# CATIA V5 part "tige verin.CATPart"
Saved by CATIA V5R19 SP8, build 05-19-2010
Part number: tige verin
Bounding box of the stored display mesh (mm): x -10 to -2, y -3 to 13.607, z -16.853 to 8.502
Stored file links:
  C:\Users\rcousturie\Desktop\EU_thinkMotion\iao\IAO_MMS_Groupe1\glenerrant\glenerrant\Nouveau dossier\tige verin.CATPart
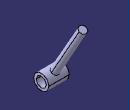
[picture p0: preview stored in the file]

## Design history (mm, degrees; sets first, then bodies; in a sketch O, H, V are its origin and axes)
Set1
  Point1: (0, 0, -14)
  Point2: (0, 13, 9)
  Plane1: type Offset, RefPlane yz-plane, Offset -2
  Plane2: type Normal, Curve Line1, RefPoint Point1
  Line1: stored without definition
Body1 (main body)
  Sketch1 on Plane1, origin (-2, 0, 0), H (0, 1, 0), V (0, 0, 1)
    circle A1 centre (0, -14) radius 3
    point P1 (0, -14)
    circle A2 centre (0, -14) radius 2
    point P2 (0, -14)
    reference projected point E1 (0, -14) from Point1
    reference projected point E2 (0, -14) from Point1
    radius A2 = 2
    radius A1 = 3
    coincidence: P2 E1, P1 E2
  Pad1: profile Sketch1, direction (-1, 0, 0), length 8
  Line2: stored without definition
  Line3: stored without definition
  Sketch2 on Plane2, origin (0, -5.9971, -10.6103), H (-1, 0, 0), V (0, -0.8706, 0.4921)
    circle A1 centre (6, -6.8888) radius 1.5
    point P1 (6, -6.8888)
    reference projected line E1 through (0, -6.8888) direction (-1, 0) from axis of face of Pad1 from Sketch1.A1
    reference projected point E2 (0, -6.8888) from Point1
    radius A1 = 1.5
    distance P1 E2 = 6
    coincidence: P1 E1
  Pad2: profile Sketch2, direction (0, 0.4921, 0.8706), length 25, opposite side length -2
  Line4: stored without definition
  Point3: stored without definition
